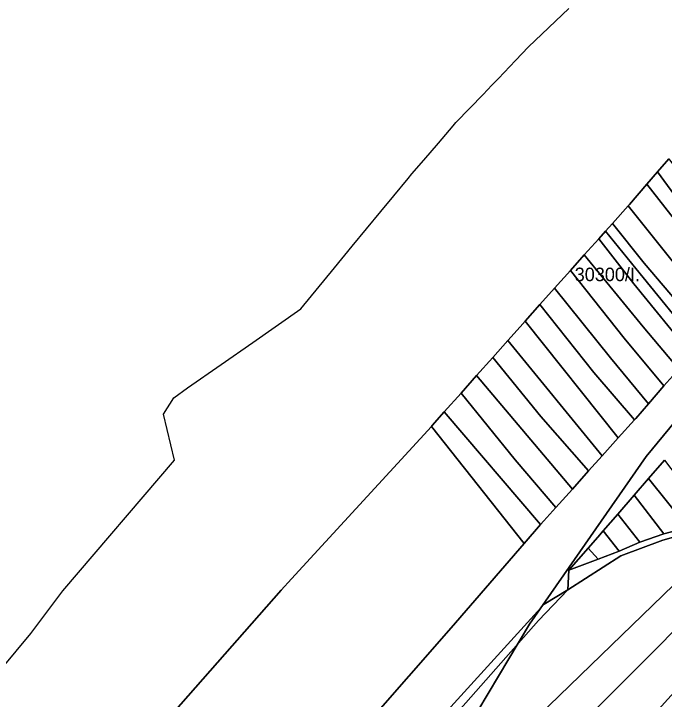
# Model space of a CAD drawing. Extents: x -537068 to -534056, y -1176840 to -1172401.
# Drawn here: x -535510.5 to -535269.7, y -1174389.8 to -1174136.1 of the extents above; entities that cross this region are included whole.
import ezdxf

# ---------------------------------------------------------------- set-up
doc = ezdxf.new("R2010")
doc.units = 0
for name, color, linetype in [('95560013', 7, 'Continuous'), ('95640013', 7, 'Continuous'), ('95660013', 7, 'Continuous')]:
    doc.layers.add(name, color=color, linetype=linetype)

msp = doc.modelspace()

# ---------------------------------------------------------------- linework, layer by layer
at = {"layer": '95560013'}
for points in [[(-535234.55, -1174233.42), (-535238.87, -1174238.39), (-535256.04, -1174216.65), (-535272.12, -1174194.62), (-535267.98, -1174189.84), (-535247.63, -1174217.13)], [(-535256.04, -1174216.65), (-535238.87, -1174238.39), (-535242.31, -1174242.35), (-535276.09, -1174199.22), (-535272.12, -1174194.62)], [(-535282.53, -1174206.66), (-535276.09, -1174199.22), (-535242.31, -1174242.35), (-535246.39, -1174247.05), (-535248.9, -1174249.93), (-535283.06, -1174207.25)], [(-535288.84, -1174213.72), (-535283.06, -1174207.25), (-535248.9, -1174249.93), (-535253.95, -1174255.73), (-535277.14, -1174228.44)], [(-535256.81, -1174259.01), (-535280.22, -1174230.42), (-535291.39, -1174216.58), (-535288.84, -1174213.72), (-535277.14, -1174228.44), (-535253.95, -1174255.73)], [(-535256.81, -1174259.01), (-535259.64, -1174262.26), (-535280.88, -1174236.02), (-535293.88, -1174219.37), (-535291.39, -1174216.58), (-535280.22, -1174230.42)], [(-535280.88, -1174236.02), (-535259.64, -1174262.26), (-535264.3, -1174267.6), (-535277.44, -1174251.99), (-535299.26, -1174225.39), (-535293.88, -1174219.37)], [(-535284.49, -1174256.23), (-535304.39, -1174231.13), (-535299.26, -1174225.39), (-535277.44, -1174251.99), (-535264.3, -1174267.6), (-535269.77, -1174273.88)], [(-535269.77, -1174273.88), (-535275.54, -1174280.5), (-535289.51, -1174263.52), (-535310.29, -1174237.73), (-535304.39, -1174231.13), (-535284.49, -1174256.23)], [(-535295.71, -1174268.85), (-535315.67, -1174243.75), (-535310.29, -1174237.73), (-535289.51, -1174263.52), (-535275.54, -1174280.5), (-535280.23, -1174285.88), (-535280.67, -1174286.37)], [(-535280.67, -1174286.37), (-535286.71, -1174293.1), (-535321.14, -1174249.88), (-535315.67, -1174243.75), (-535295.71, -1174268.85)], [(-535286.71, -1174293.1), (-535292.62, -1174299.68), (-535327.51, -1174257.03), (-535323, -1174251.96), (-535321.14, -1174249.88)], [(-535333.17, -1174263.38), (-535327.51, -1174257.03), (-535292.62, -1174299.68), (-535297.67, -1174305.31), (-535315.36, -1174285.15)], [(-535303.68, -1174312.01), (-535339.12, -1174270.06), (-535333.17, -1174263.38), (-535315.36, -1174285.15), (-535297.67, -1174305.31)], [(-535344.87, -1174276.52), (-535339.12, -1174270.06), (-535303.68, -1174312.01), (-535309.79, -1174318.83), (-535324.82, -1174301.16)], [(-535351.08, -1174283.49), (-535344.87, -1174276.52), (-535324.82, -1174301.16), (-535309.79, -1174318.83), (-535314.2, -1174323.75), (-535315.43, -1174325.17)], [(-535315.43, -1174325.17), (-535321.49, -1174332.16), (-535355.87, -1174288.85), (-535355.58, -1174288.54), (-535351.08, -1174283.49)], [(-535355.87, -1174288.85), (-535321.49, -1174332.16), (-535348.53, -1174363.33), (-535379.86, -1174399.13), (-535391.37, -1174399.48), (-535403.52, -1174412.4), (-535427.89, -1174431.5), (-535433.97, -1174438.85), (-535451.22, -1174452.76), (-535457.65, -1174459.35), (-535483.27, -1174431.05), (-535482.99, -1174430.74), (-535411.51, -1174349.5), (-535407.64, -1174345.3)], [(-535252, -1174324.43), (-535260.98, -1174326.2), (-535275.5, -1174308.18), (-535269.54, -1174301.33)], [(-535260.98, -1174326.2), (-535269.77, -1174328.55), (-535280.86, -1174314.35), (-535275.5, -1174308.18)], [(-535286.89, -1174321.3), (-535280.86, -1174314.35), (-535269.77, -1174328.55), (-535278.72, -1174331.67)], [(-535292.22, -1174327.44), (-535286.89, -1174321.3), (-535278.72, -1174331.67), (-535286.39, -1174334.96)], [(-535343.24, -1174443.42), (-535312.34, -1174410.85), (-535225.53, -1174323.91), (-535208.35, -1174323.62), (-535301.92, -1174426.82), (-535371.59, -1174503.77), (-535373.15, -1174495.04), (-535369.14, -1174473.07)], [(-535243.22, -1174325.3), (-535225.53, -1174323.91), (-535312.34, -1174410.85), (-535343.24, -1174443.42), (-535369.14, -1174473.07), (-535354.31, -1174434.77), (-535327.65, -1174407.04)], [(-535260.14, -1174328.1), (-535250.07, -1174325.96), (-535243.22, -1174325.3), (-535327.65, -1174407.04), (-535354.31, -1174434.77), (-535353.02, -1174415.23), (-535355.76, -1174406.02), (-535353.37, -1174402.75), (-535316.18, -1174360.73), (-535305.32, -1174349.34), (-535285.73, -1174336.78), (-535270.21, -1174330.97)], [(-535286.39, -1174334.96), (-535294.18, -1174337.94), (-535297.83, -1174333.87), (-535294.26, -1174329.79), (-535292.22, -1174327.44)], [(-535297.83, -1174333.87), (-535294.18, -1174337.94), (-535305.02, -1174342.09)], [(-535369.36, -1174417.88), (-535352.34, -1174396.71), (-535314.14, -1174354.58), (-535305.32, -1174349.34), (-535316.18, -1174360.73), (-535353.37, -1174402.75), (-535355.76, -1174406.02), (-535360.25, -1174412.16), (-535364.03, -1174417.33), (-535372.93, -1174427.69), (-535373.7, -1174428.54)]]:
    msp.add_lwpolyline(points, close=True, dxfattribs=at)
msp.add_lwpolyline([(-535260.14, -1174328.1), (-535270.21, -1174330.97), (-535285.73, -1174336.78), (-535305.32, -1174349.34), (-535305.02, -1174342.09), (-535294.18, -1174337.94), (-535286.39, -1174334.96), (-535278.72, -1174331.67), (-535269.77, -1174328.55), (-535260.98, -1174326.2)], dxfattribs=at)
at = {"layer": '95640013'}
for points in [[(-535520.55, -1174385.1), (-535504.07, -1174365.48), (-535492.31, -1174349.7), (-535450.96, -1174301.35), (-535455.08, -1174284.3), (-535451.26, -1174278.21), (-535446.1, -1174274.61), (-535433.68, -1174265.95), (-535421.96, -1174257.77), (-535404.15, -1174245.34), (-535391.72, -1174230.21), (-535385.13, -1174222.19), (-535379.83, -1174215.74), (-535374.56, -1174209.32), (-535369.77, -1174203.48), (-535364.5, -1174197.07), (-535363.11, -1174195.38), (-535358.7, -1174190.27), (-535353.27, -1174183.96), (-535347.82, -1174177.64), (-535346.76, -1174176.41), (-535341.63, -1174171.07), (-535336.76, -1174165.99), (-535333.45, -1174162.54), (-535331.04, -1174160.02), (-535324.74, -1174153.45), (-535319.89, -1174148.39), (-535304.97, -1174134.18)], [(-535267.98, -1174189.84), (-535272.12, -1174194.62), (-535276.09, -1174199.22), (-535282.53, -1174206.66), (-535283.06, -1174207.25), (-535288.84, -1174213.72), (-535291.39, -1174216.58), (-535293.88, -1174219.37), (-535299.26, -1174225.39), (-535304.39, -1174231.13), (-535310.29, -1174237.73), (-535315.67, -1174243.75), (-535321.14, -1174249.88), (-535323, -1174251.96), (-535327.51, -1174257.03), (-535333.17, -1174263.38), (-535339.12, -1174270.06), (-535344.87, -1174276.52), (-535351.08, -1174283.49), (-535355.58, -1174288.54), (-535355.87, -1174288.85), (-535407.64, -1174345.3), (-535411.51, -1174349.5), (-535482.99, -1174430.74)], [(-535379.86, -1174399.13), (-535348.53, -1174363.33), (-535321.49, -1174332.16), (-535315.43, -1174325.17), (-535314.2, -1174323.75), (-535309.79, -1174318.83), (-535303.68, -1174312.01), (-535297.67, -1174305.31), (-535292.62, -1174299.68), (-535286.71, -1174293.1), (-535280.67, -1174286.37), (-535280.23, -1174285.88), (-535275.54, -1174280.5), (-535269.77, -1174273.88), (-535264.3, -1174267.6)], [(-535269.54, -1174301.33), (-535275.5, -1174308.18), (-535280.86, -1174314.35), (-535286.89, -1174321.3), (-535292.22, -1174327.44), (-535294.26, -1174329.79), (-535297.83, -1174333.87), (-535305.02, -1174342.09), (-535305.32, -1174349.34), (-535314.14, -1174354.58), (-535352.34, -1174396.71)]]:
    msp.add_lwpolyline(points, dxfattribs=at)
at = {"layer": '95660013'}
for points in [[(-535100.87, -1174125), (-535117.31, -1174137), (-535148, -1174158), (-535195.62, -1174212), (-535248.37, -1174266), (-535276.31, -1174300), (-535319.5, -1174362), (-535346.37, -1174407), (-535367.5, -1174451), (-535378.12, -1174486), (-535380, -1174518), (-535374.31, -1174561), (-535368.5, -1174584), (-535365.69, -1174603), (-535385.73, -1174589.5), (-535419.12, -1174567), (-535444.62, -1174545), (-535468.62, -1174524), (-535480.12, -1174503), (-535499.81, -1174477), (-535514.37, -1174459)], [(-535345.13, -1174617.25), (-535365.69, -1174603), (-535368.5, -1174584), (-535374.31, -1174561), (-535380, -1174518), (-535378.12, -1174486), (-535367.5, -1174451), (-535346.37, -1174407), (-535319.5, -1174362), (-535276.31, -1174300), (-535248.37, -1174266), (-535195.62, -1174212), (-535148, -1174158), (-535117.31, -1174137), (-535100.87, -1174125)], [(-535520.55, -1174385.1), (-535504.07, -1174365.48), (-535492.31, -1174349.7), (-535450.96, -1174301.35), (-535455.08, -1174284.3), (-535451.26, -1174278.21), (-535446.1, -1174274.61), (-535433.68, -1174265.95), (-535421.96, -1174257.77), (-535404.15, -1174245.34), (-535391.72, -1174230.21), (-535385.13, -1174222.19), (-535379.83, -1174215.74), (-535374.56, -1174209.32), (-535369.77, -1174203.48), (-535364.5, -1174197.07), (-535363.11, -1174195.38), (-535358.7, -1174190.27), (-535353.27, -1174183.96), (-535347.82, -1174177.64), (-535346.76, -1174176.41), (-535341.63, -1174171.07), (-535336.76, -1174165.99), (-535333.45, -1174162.54), (-535331.04, -1174160.02), (-535324.74, -1174153.45), (-535319.89, -1174148.39), (-535304.97, -1174134.18)]]:
    msp.add_lwpolyline(points, dxfattribs=at)

# ---------------------------------------------------------------- texts
msp.add_text('30300/I.', height=5, rotation=360, dxfattribs=at).set_placement((-535302.82, -1174235.09))

doc.saveas('drawing.dxf')
